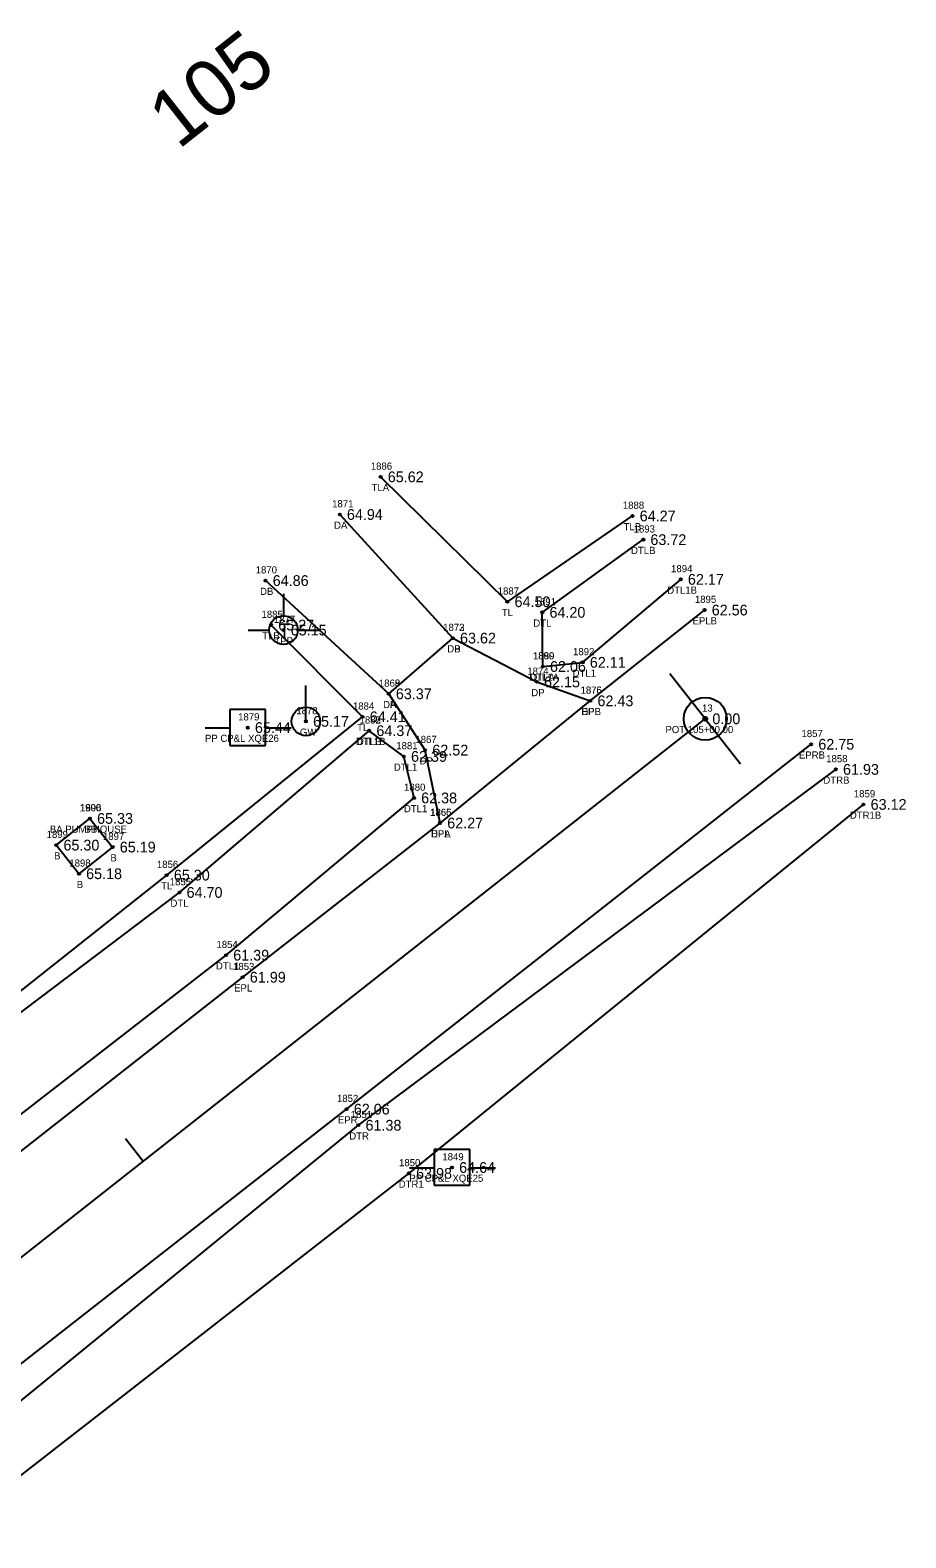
# Model space of a CAD drawing. Extents: x 2420113 to 2422887, y 845323 to 846653.
# Drawn here: x 2422548.3 to 2422670.7, y 846359.2 to 846569.9 of the extents above; entities that cross this region are included whole.
import ezdxf

# ---------------------------------------------------------------- set-up
doc = ezdxf.new("R2010")
doc.units = 0
for name, color, linetype in [('RD_EX_Bldg', 7, 'Continuous'), ('RD_EX_Bldg_txCode', 7, 'Continuous'), ('RD_EX_Driveway', 7, 'Continuous'), ('RD_EX_Driveway_txCode', 7, 'Continuous'), ('RD_EX_H2O', 7, 'Continuous'), ('RD_EX_H2O_txCode', 7, 'Continuous'), ('RD_EX_Road', 7, 'Continuous'), ('RD_EX_Road_txCode', 7, 'Continuous'), ('RD_EX_TX_Bldg_ELEV', 7, 'Continuous'), ('RD_EX_TX_Driveway_ELEV', 7, 'Continuous'), ('RD_EX_TX_H2O_ELEV', 7, 'Continuous'), ('RD_EX_TX_Road_ELEV', 7, 'Continuous'), ('RD_EX_TX_UT_ELEV', 7, 'Continuous'), ('RD_EX_TX_VEG_ELEV', 7, 'Continuous'), ('RD_EX_UT', 7, 'Continuous'), ('RD_EX_UT_txCode', 7, 'Continuous'), ('RD_EX_VEG', 7, 'Continuous'), ('RD_EX_VEG_txCode', 7, 'Continuous'), ('RD_HC_Cl', 7, 'Continuous'), ('RD_HC_Data', 7, 'Continuous'), ('RD_HC_Data_Tic', 7, 'Continuous'), ('RD_HC_Survey_ELEV', 7, 'Continuous'), ('RD_HC_TX_Sta50', 7, 'Continuous'), ('RD_HC_txCode', 7, 'Continuous'), ('RD_SMD_Locator', 7, 'Continuous')]:
    doc.layers.add(name, color=color, linetype=linetype)

msp = doc.modelspace()

# ---------------------------------------------------------------- linework, layer by layer
at = {"layer": 'RD_EX_Bldg'}
msp.add_lwpolyline([(2422556.7, 846459.73), (2422559.87, 846455.73), (2422555.17, 846452), (2422552, 846456), (2422556.7, 846459.73)], dxfattribs=at)
at = {"layer": 'RD_EX_Driveway'}
for p, q in [((2422591.62, 846502.22), (2422607.43, 846484.94)), ((2422598.46, 846477.15), (2422581.25, 846492.98))]:
    msp.add_line(p, q, dxfattribs=at)
msp.add_lwpolyline([(2422605.64, 846459.09), (2422603.56, 846469.28), (2422598.46, 846477.15), (2422607.43, 846484.94), (2422619.17, 846478.82), (2422626.64, 846476.17)], dxfattribs=at)
at = {"layer": 'RD_EX_H2O'}
for points in [[(2422620, 846480.97), (2422619.93, 846488.54), (2422634.04, 846498.7)], [(2422620, 846480.97), (2422625.57, 846481.55), (2422639.28, 846493.15)], [(2422472.83, 846361.25), (2422468.68, 846366.81), (2422492.83, 846391.64), (2422569.21, 846449.39), (2422595.74, 846472)], [(2422472.83, 846361.25), (2422499.74, 846381.72), (2422575.73, 846440.62), (2422602, 846462.6), (2422600.58, 846468.4), (2422595.74, 846472)], [(2422383.12, 846248.84), (2422451.79, 846302.96), (2422519.84, 846356.14), (2422594.22, 846416.85), (2422660.96, 846466.59)], [(2422383.12, 846248.84), (2422386.53, 846244.46), (2422456.45, 846298.4), (2422524.56, 846350.4), (2422601.29, 846410.12), (2422664.82, 846461.69)]]:
    msp.add_lwpolyline(points, dxfattribs=at)
at = {"layer": 'RD_EX_Road'}
for points in [[(2421810.77, 845819.82), (2421809.69, 845832.82), (2421803.88, 845842.86), (2421852.96, 845873.69), (2421939.48, 845935.12), (2421980.78, 845967.01), (2422140.12, 846092.81), (2422210.03, 846148.43), (2422282.88, 846205.21), (2422291.79, 846212.09), (2422354.49, 846261.98), (2422400.82, 846297.88), (2422417.34, 846311.65), (2422435.4, 846324.77), (2422462.49, 846346.77), (2422472.85, 846354.85), (2422502.3, 846378.16), (2422578.05, 846437.54), (2422605.64, 846459.09), (2422626.64, 846476.17), (2422642.61, 846488.86)], [(2421810.77, 845819.82), (2421865.31, 845853.52), (2421953.26, 845916.07), (2421995.06, 845948.03), (2422068.36, 846005.98), (2422153.46, 846073.36), (2422229.55, 846134.03), (2422245.4, 846145.63), (2422297.08, 846186.88), (2422369.77, 846243.69), (2422382.04, 846253.08), (2422449.02, 846305.97), (2422517.14, 846360.1), (2422592.58, 846419.1), (2422657.51, 846470.1)]]:
    msp.add_lwpolyline(points, dxfattribs=at)
at = {"layer": 'RD_EX_UT'}
for p, q in [((2422583.76, 846491.13), (2422583.76, 846488.06)), ((2422578.83, 846486.07), (2422581.76, 846486.07)), ((2422585.76, 846486.07), (2422588.83, 846486.07)), ((2422586.89, 846473.3), (2422586.89, 846478.3)), ((2422581.25, 846474.94), (2422576.25, 846474.94)), ((2422576.25, 846474.94), (2422576.25, 846469.94)), ((2422581.25, 846469.94), (2422581.25, 846474.94)), ((2422572.82, 846472.38), (2422576.29, 846472.38)), ((2422581.18, 846472.38), (2422584.82, 846472.38)), ((2422576.25, 846469.94), (2422581.25, 846469.94)), ((2422609.8, 846413.45), (2422604.8, 846413.45)), ((2422604.8, 846413.45), (2422604.8, 846408.45)), ((2422609.8, 846408.45), (2422609.8, 846413.45)), ((2422601.37, 846410.88), (2422604.84, 846410.88)), ((2422609.73, 846410.88), (2422613.37, 846410.88)), ((2422604.8, 846408.45), (2422609.8, 846408.45))]:
    msp.add_line(p, q, dxfattribs=at)
for centre in [(2422583.76, 846486.06), (2422586.89, 846473.3)]:
    msp.add_circle(centre, 2, dxfattribs=at)
at = {"layer": 'RD_EX_VEG'}
for points in [[(2422597.33, 846507.48), (2422615.05, 846490.02), (2422632.54, 846502.01)], [(2422433.26, 846435.15), (2422477.57, 846380.54), (2422567.43, 846451.81), (2422594.81, 846473.94), (2422582.02, 846486.76)]]:
    msp.add_lwpolyline(points, dxfattribs=at)
at = {"layer": 'RD_HC_Cl'}
msp.add_line((2421944.32, 845923.85), (2422642.7, 846473.66), dxfattribs=at)
at = {"layer": 'RD_HC_Data'}
for radius in [3, 0.282]:
    msp.add_circle((2422642.7, 846473.66), radius, dxfattribs=at)
at = {"layer": 'RD_HC_Data_Tic'}
for p, q in [((2422642.69, 846473.66), (2422637.75, 846479.94)), ((2422642.69, 846473.66), (2422647.64, 846467.37)), ((2422564.12, 846411.8), (2422561.65, 846414.94))]:
    msp.add_line(p, q, dxfattribs=at)
at = {"layer": 'RD_SMD_Locator'}
for centre in [(2422597.33, 846507.48), (2422591.62, 846502.22), (2422632.54, 846502.01), (2422634.04, 846498.7), (2422581.25, 846492.98), (2422639.28, 846493.15), (2422615.05, 846490.02), (2422619.93, 846488.54), (2422642.61, 846488.86), (2422582.02, 846486.76), (2422583.76, 846486.06), (2422607.43, 846484.94), (2422607.43, 846484.94), (2422620, 846480.97), (2422620, 846480.97), (2422625.57, 846481.55), (2422619.17, 846478.82), (2422598.46, 846477.15), (2422598.46, 846477.15), (2422626.64, 846476.17), (2422626.64, 846476.17), (2422586.89, 846473.3), (2422594.81, 846473.94), (2422642.7, 846473.66), (2422578.76, 846472.43), (2422595.74, 846472), (2422595.74, 846472), (2422603.56, 846469.28), (2422657.51, 846470.1), (2422600.58, 846468.4), (2422660.96, 846466.59), (2422602, 846462.6), (2422664.82, 846461.69), (2422556.7, 846459.73), (2422556.7, 846459.73), (2422605.64, 846459.09), (2422605.64, 846459.09), (2422552, 846456), (2422559.87, 846455.73), (2422555.17, 846452), (2422567.43, 846451.81), (2422569.21, 846449.39), (2422575.73, 846440.62), (2422578.05, 846437.54), (2422592.58, 846419.1), (2422594.22, 846416.85), (2422601.29, 846410.12), (2422607.31, 846410.94)]:
    msp.add_circle(centre, 0.15, dxfattribs=at)

# ---------------------------------------------------------------- texts
at = {"layer": 'RD_EX_Bldg_txCode'}
for s, p in [('1900', (2422555.28, 846460.73)), ('1896', (2422555.33, 846460.73)), ('BA PUMPHOUSE', (2422551.1, 846457.73)), ('BB', (2422555.93, 846457.73)), ('1899', (2422550.65, 846457)), ('1897', (2422558.52, 846456.73)), ('B', (2422551.69, 846454)), ('B', (2422559.56, 846453.73)), ('1898', (2422553.82, 846453)), ('B', (2422554.86, 846450))]:
    msp.add_text(s, height=1, dxfattribs=at).set_placement(p)
at = {"layer": 'RD_EX_Driveway_txCode'}
for s, p in [('1871', (2422590.56, 846503.22)), ('DA', (2422590.82, 846500.22)), ('1870', (2422579.87, 846493.98)), ('DB', (2422580.48, 846490.98)), ('1872', (2422606.08, 846485.94)), ('1873', (2422606.08, 846485.94)), ('DB', (2422606.65, 846482.94)), ('DP', (2422606.65, 846482.94)), ('1874', (2422617.83, 846479.82)), ('1868', (2422597.09, 846478.15)), ('1869', (2422597.09, 846478.15)), ('DP', (2422618.39, 846476.82)), ('1875', (2422625.29, 846477.17)), ('DA', (2422597.67, 846475.15)), ('DP', (2422597.68, 846475.15)), ('DPB', (2422625.39, 846474.17)), ('1867', (2422602.19, 846470.28)), ('DP', (2422602.78, 846467.28)), ('1866', (2422604.24, 846460.09)), ('DPA', (2422604.37, 846457.09))]:
    msp.add_text(s, height=1, dxfattribs=at).set_placement(p)
at = {"layer": 'RD_EX_H2O_txCode'}
for s, p in [('1893', (2422632.7, 846499.7)), ('DTLB', (2422632.33, 846496.7)), ('1894', (2422637.93, 846494.15)), ('1891', (2422618.86, 846489.54)), ('DTL1B', (2422637.39, 846491.15)), ('DTL', (2422618.68, 846486.54)), ('1890', (2422618.61, 846481.97)), ('1889', (2422618.65, 846481.97)), ('1892', (2422624.23, 846482.55)), ('DTL1A', (2422618.1, 846478.97)), ('DTLA', (2422618.27, 846478.97)), ('DTL1', (2422624.16, 846479.55)), ('1882', (2422594.39, 846473)), ('1883', (2422594.39, 846473)), ('DTL1B', (2422593.86, 846470)), ('DTLB', (2422594.02, 846470)), ('1881', (2422599.52, 846469.4)), ('DTL1', (2422599.18, 846466.4)), ('1858', (2422659.61, 846467.59)), ('DTRB', (2422659.22, 846464.59)), ('1880', (2422600.61, 846463.6)), ('1859', (2422663.48, 846462.69)), ('DTL1', (2422600.59, 846460.6)), ('DTR1B', (2422662.92, 846459.69)), ('1855', (2422567.86, 846450.39)), ('DTL', (2422567.96, 846447.39)), ('1854', (2422574.39, 846441.62)), ('DTL1', (2422574.32, 846438.62)), ('1851', (2422593.16, 846417.85)), ('DTR', (2422592.95, 846414.85)), ('1850', (2422599.91, 846411.12)), ('DTR1', (2422599.86, 846408.12))]:
    msp.add_text(s, height=1, dxfattribs=at).set_placement(p)
at = {"layer": 'RD_EX_Road_txCode'}
for s, p in [('1895', (2422641.26, 846489.86)), ('EPLB', (2422640.93, 846486.86)), ('1876', (2422625.27, 846477.17)), ('EPL', (2422625.43, 846474.17)), ('1857', (2422656.16, 846471.1)), ('EPRB', (2422655.8, 846468.1)), ('1865', (2422604.27, 846460.09)), ('EPL', (2422604.43, 846457.09)), ('1853', (2422576.71, 846438.54)), ('EPL', (2422576.85, 846435.54)), ('1852', (2422591.23, 846420.1)), ('EPR', (2422591.35, 846417.1))]:
    msp.add_text(s, height=1, dxfattribs=at).set_placement(p)
at = {"layer": 'RD_EX_TX_Bldg_ELEV'}
for s, p in [('65.33', (2422557.7, 846458.98)), ('65.33', (2422557.7, 846458.98)), ('65.30', (2422553, 846455.25)), ('65.19', (2422560.87, 846454.98)), ('65.18', (2422556.17, 846451.25))]:
    msp.add_text(s, height=1.5, dxfattribs=at).set_placement(p)
at = {"layer": 'RD_EX_TX_Driveway_ELEV'}
for s, p in [('64.94', (2422592.62, 846501.47)), ('64.86', (2422582.25, 846492.23)), ('63.62', (2422608.43, 846484.19)), ('63.62', (2422608.43, 846484.19)), ('63.37', (2422599.46, 846476.4)), ('63.37', (2422599.46, 846476.4)), ('62.15', (2422620.17, 846478.07)), ('62.43', (2422627.64, 846475.42)), ('62.52', (2422604.56, 846468.53)), ('62.27', (2422606.64, 846458.34))]:
    msp.add_text(s, height=1.5, dxfattribs=at).set_placement(p)
at = {"layer": 'RD_EX_TX_H2O_ELEV'}
for s, p in [('63.72', (2422635.04, 846497.95)), ('62.17', (2422640.28, 846492.4)), ('64.20', (2422620.93, 846487.79)), ('62.11', (2422626.57, 846480.8)), ('62.06', (2422621, 846480.22)), ('62.06', (2422621, 846480.22)), ('64.37', (2422596.74, 846471.25)), ('64.37', (2422596.74, 846471.25)), ('62.39', (2422601.58, 846467.65)), ('61.93', (2422661.96, 846465.84)), ('62.38', (2422603, 846461.85)), ('63.12', (2422665.82, 846460.94)), ('64.70', (2422570.21, 846448.64)), ('61.39', (2422576.73, 846439.87)), ('61.38', (2422595.22, 846416.1)), ('63.98', (2422602.29, 846409.37))]:
    msp.add_text(s, height=1.5, dxfattribs=at).set_placement(p)
at = {"layer": 'RD_EX_TX_Road_ELEV'}
for s, p in [('62.56', (2422643.61, 846488.11)), ('62.43', (2422627.64, 846475.42)), ('62.75', (2422658.51, 846469.35)), ('62.27', (2422606.64, 846458.34)), ('61.99', (2422579.05, 846436.79)), ('62.06', (2422593.58, 846418.35))]:
    msp.add_text(s, height=1.5, dxfattribs=at).set_placement(p)
at = {"layer": 'RD_EX_TX_UT_ELEV'}
for s, p in [('65.15', (2422584.76, 846485.31)), ('65.17', (2422587.89, 846472.55))]:
    msp.add_text(s, height=1.5, dxfattribs=at).set_placement(p)
at = {"layer": 'RD_EX_TX_VEG_ELEV'}
for s, p in [('65.62', (2422598.33, 846506.73)), ('64.27', (2422633.54, 846501.26)), ('64.50', (2422616.05, 846489.27)), ('65.27', (2422583.02, 846486.01)), ('64.41', (2422595.81, 846473.19)), ('65.30', (2422568.43, 846451.06))]:
    msp.add_text(s, height=1.5, dxfattribs=at).set_placement(p)
at = {"layer": 'RD_EX_UT'}
msp.add_text('T', height=2, dxfattribs=at).set_placement((2422583.09, 846485.01))
at = {"layer": 'RD_EX_UT_txCode'}
for s, p in [('1877', (2422582.41, 846487.06)), ('TPP', (2422582.49, 846484.06)), ('1879', (2422577.42, 846473.43)), ('1878', (2422585.54, 846474.3)), ('PP CP&L XQE26', (2422572.78, 846470.43)), ('GW', (2422586.05, 846471.3)), ('1849', (2422605.96, 846411.94)), ('PP CP&L XQE25', (2422601.35, 846408.94))]:
    msp.add_text(s, height=1, dxfattribs=at).set_placement(p)
at = {"layer": 'RD_EX_VEG_txCode'}
for s, p in [('1886', (2422595.96, 846508.48)), ('TLA', (2422596.07, 846505.48)), ('1888', (2422631.19, 846503.01)), ('TLB', (2422631.29, 846500.01)), ('1887', (2422613.7, 846491.02)), ('1885', (2422580.68, 846487.76)), ('TL', (2422614.27, 846488.02)), ('TLB', (2422580.78, 846484.76)), ('1884', (2422593.46, 846474.94)), ('TL', (2422594.04, 846471.94)), ('1856', (2422566.06, 846452.81)), ('TL', (2422566.66, 846449.81))]:
    msp.add_text(s, height=1, dxfattribs=at).set_placement(p)
at = {"layer": 'RD_HC_Survey_ELEV'}
for s, p in [('0.00', (2422643.7, 846472.91)), ('65.44', (2422579.76, 846471.68)), ('64.64', (2422608.31, 846410.19))]:
    msp.add_text(s, height=1.5, dxfattribs=at).set_placement(p)
at = {"layer": 'RD_HC_TX_Sta50'}
msp.add_text('105', height=8, rotation=38.2121, dxfattribs=at).set_placement((2422569.05, 846553.13))
at = {"layer": 'RD_HC_txCode'}
for s, p in [('13', (2422642.25, 846474.66)), ('POT 105+00.00', (2422637.14, 846471.66))]:
    msp.add_text(s, height=1, dxfattribs=at).set_placement(p)

doc.saveas('drawing.dxf')
